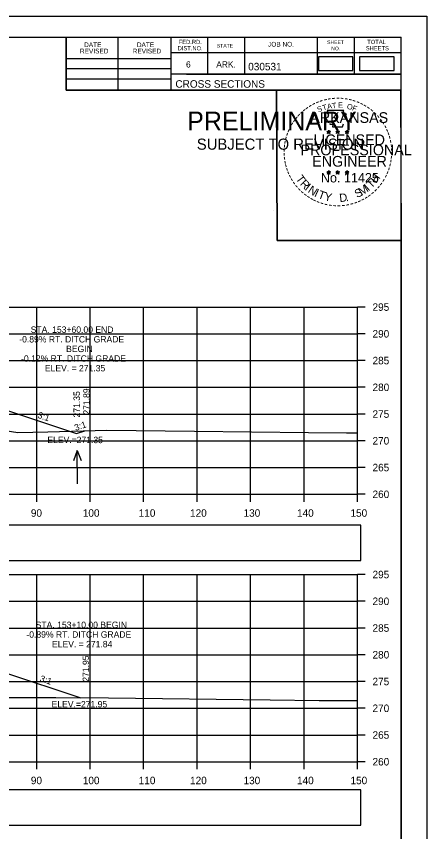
# Model space of a CAD drawing. Extents: x 285 to 4233, y -659 to 3710.
# Drawn here: x 1309.9 to 1386.6, y 19.8 to 172.2 of the extents above; entities that cross this region are included whole.
import ezdxf

# ---------------------------------------------------------------- set-up
doc = ezdxf.new("R2010")
doc.units = 0
for name, color, linetype in [('R_Axis', 7, 'Continuous'), ('R_Axis Annot', 7, 'Continuous'), ('R_Border', 7, 'Continuous'), ('R_Border PE', 7, 'Continuous'), ('R_Border Prem', 7, 'Continuous'), ('R_Exist Surface', 7, 'Continuous'), ('R_Fin Surface', 7, 'Continuous'), ('R_Grid', 7, 'Continuous'), ('R_No Plot', 7, 'Continuous'), ('R_Water Annot', 7, 'Continuous'), ('R_Xsect Elev', 7, 'Continuous'), ('R_Xsect Slope', 7, 'Continuous')]:
    doc.layers.add(name, color=color, linetype=linetype)

msp = doc.modelspace()

# ---------------------------------------------------------------- linework, layer by layer
at = {"layer": 'R_Axis'}
for p, q in [((1373.68, 82.87), (1373.68, 117.87)), ((1375.08, 117.87), (1373.68, 117.87)), ((1375.08, 112.87), (1373.68, 112.87)), ((1375.08, 107.87), (1373.68, 107.87)), ((1375.08, 102.87), (1373.68, 102.87)), ((1375.08, 97.87), (1373.68, 97.87)), ((1375.08, 92.87), (1373.68, 92.87)), ((1375.08, 87.87), (1373.68, 87.87)), ((1073.68, 82.87), (1373.68, 82.87)), ((1313.68, 81.47), (1313.68, 82.87)), ((1323.68, 81.47), (1323.68, 82.87)), ((1333.68, 81.47), (1333.68, 82.87)), ((1343.68, 81.47), (1343.68, 82.87)), ((1353.68, 81.47), (1353.68, 82.87)), ((1363.68, 81.47), (1363.68, 82.87)), ((1373.68, 81.47), (1373.68, 82.87)), ((1375.08, 82.87), (1373.68, 82.87)), ((1373.68, 32.87), (1373.68, 67.87)), ((1375.08, 67.87), (1373.68, 67.87)), ((1375.08, 62.87), (1373.68, 62.87)), ((1375.08, 57.87), (1373.68, 57.87)), ((1375.08, 52.87), (1373.68, 52.87)), ((1375.08, 47.87), (1373.68, 47.87)), ((1375.08, 42.87), (1373.68, 42.87)), ((1375.08, 37.87), (1373.68, 37.87)), ((1073.68, 32.87), (1373.68, 32.87)), ((1313.68, 31.47), (1313.68, 32.87)), ((1323.68, 31.47), (1323.68, 32.87)), ((1333.68, 31.47), (1333.68, 32.87)), ((1343.68, 31.47), (1343.68, 32.87)), ((1353.68, 31.47), (1353.68, 32.87)), ((1363.68, 31.47), (1363.68, 32.87)), ((1373.68, 31.47), (1373.68, 32.87)), ((1375.08, 32.87), (1373.68, 32.87))]:
    msp.add_line(p, q, dxfattribs=at)
at = {"layer": 'R_Axis Annot'}
for points in [[(1366.36, 162.12), (1372.81, 162.12), (1372.81, 164.68), (1366.36, 164.68)], [(1374.05, 162.12), (1380.51, 162.12), (1380.51, 164.68), (1374.05, 164.68)], [(1234.32, 70.47), (1374.32, 70.47), (1374.32, 77.12), (1234.32, 77.12)], [(1234.32, 20.99), (1374.32, 20.99), (1374.32, 27.65), (1234.32, 27.65)]]:
    msp.add_lwpolyline(points, close=True, dxfattribs=at)
at = {"layer": 'R_Border'}
for p, q in [((1065.68, 168.33), (1381.86, 168.33)), ((1319.22, 158.45), (1319.22, 168.33)), ((1328.9, 158.45), (1328.9, 168.33)), ((1338.76, 168.33), (1338.76, 158.45)), ((1345.6, 168.33), (1345.6, 161.39)), ((1352.54, 168.33), (1352.54, 161.39)), ((1366.12, 168.33), (1366.12, 161.39)), ((1373.06, 168.33), (1373.06, 161.39)), ((1381.86, -37.13), (1381.86, 168.33)), ((1381.86, 165.39), (1338.76, 165.39)), ((1381.86, 165.41), (1381.86, 165.41)), ((1319.22, 164.31), (1338.76, 164.31)), ((1319.22, 162.45), (1338.76, 162.45)), ((1319.22, 160.51), (1338.76, 160.51)), ((1381.86, 161.39), (1338.76, 161.39)), ((1341.72, 161.39), (1381.86, 161.39)), ((1381.86, 158.45), (1319.22, 158.45))]:
    msp.add_line(p, q, dxfattribs=at)
at = {"layer": 'R_Border PE'}
for p, q in [((1368.29, 150.96), (1368.25, 150.71)), ((1368.29, 150.6), (1368.29, 150.96)), ((1368.29, 150.96), (1368.34, 150.71)), ((1369.96, 150.96), (1369.92, 150.71)), ((1369.96, 150.6), (1369.96, 150.96)), ((1369.96, 150.96), (1370.01, 150.71)), ((1371.72, 150.95), (1371.68, 150.7)), ((1371.72, 150.59), (1371.72, 150.95)), ((1371.72, 150.95), (1371.77, 150.7)), ((1367.94, 150.71), (1368.29, 150.6)), ((1367.94, 150.71), (1368.19, 150.66)), ((1367.94, 150.71), (1368.18, 150.59)), ((1368.07, 150.3), (1368.29, 150.6)), ((1368.07, 150.3), (1368.2, 150.54)), ((1368.07, 150.3), (1368.29, 150.52)), ((1368.64, 150.71), (1368.29, 150.6)), ((1368.5, 150.3), (1368.29, 150.6)), ((1368.5, 150.3), (1368.29, 150.51)), ((1368.64, 150.71), (1368.35, 150.66)), ((1368.5, 150.3), (1368.37, 150.59)), ((1368.64, 150.71), (1368.43, 150.61)), ((1369.61, 150.71), (1369.96, 150.6)), ((1369.61, 150.71), (1369.86, 150.66)), ((1369.61, 150.71), (1369.85, 150.59)), ((1369.74, 150.3), (1369.96, 150.6)), ((1369.74, 150.3), (1369.87, 150.54)), ((1369.74, 150.3), (1369.96, 150.52)), ((1370.31, 150.71), (1369.96, 150.6)), ((1370.17, 150.3), (1369.96, 150.6)), ((1370.17, 150.3), (1369.96, 150.51)), ((1370.31, 150.71), (1370.02, 150.66)), ((1370.17, 150.3), (1370.04, 150.59)), ((1370.31, 150.71), (1370.1, 150.61)), ((1371.38, 150.7), (1371.72, 150.59)), ((1371.38, 150.7), (1371.63, 150.65)), ((1371.38, 150.7), (1371.61, 150.57)), ((1371.51, 150.29), (1371.72, 150.59)), ((1371.51, 150.29), (1371.63, 150.53)), ((1371.51, 150.29), (1371.72, 150.51)), ((1372.07, 150.7), (1371.72, 150.59)), ((1371.94, 150.29), (1371.72, 150.59)), ((1371.94, 150.29), (1371.72, 150.5)), ((1372.07, 150.7), (1371.79, 150.65)), ((1371.94, 150.29), (1371.8, 150.58)), ((1372.07, 150.7), (1371.87, 150.59)), ((1368.29, 143.39), (1368.25, 143.14)), ((1368.29, 143.02), (1368.29, 143.39)), ((1368.29, 143.39), (1368.34, 143.14)), ((1369.96, 143.39), (1369.91, 143.14)), ((1369.96, 143.02), (1369.96, 143.39)), ((1369.96, 143.39), (1370, 143.14)), ((1371.72, 143.38), (1371.68, 143.13)), ((1371.72, 143.01), (1371.72, 143.38)), ((1371.72, 143.38), (1371.77, 143.13)), ((1367.94, 143.14), (1368.29, 143.02)), ((1367.94, 143.14), (1368.19, 143.09)), ((1367.94, 143.14), (1368.17, 143.01)), ((1368.07, 142.73), (1368.29, 143.02)), ((1368.07, 142.73), (1368.2, 142.97)), ((1368.07, 142.73), (1368.28, 142.94)), ((1368.5, 142.73), (1368.28, 142.94)), ((1368.63, 143.14), (1368.29, 143.02)), ((1368.5, 142.73), (1368.29, 143.02)), ((1368.63, 143.14), (1368.35, 143.09)), ((1368.5, 142.73), (1368.36, 143.02)), ((1368.63, 143.14), (1368.43, 143.03)), ((1369.61, 143.14), (1369.96, 143.02)), ((1369.61, 143.14), (1369.86, 143.09)), ((1369.61, 143.14), (1369.84, 143.01)), ((1369.74, 142.73), (1369.96, 143.02)), ((1369.74, 142.73), (1369.87, 142.97)), ((1369.74, 142.73), (1369.95, 142.94)), ((1370.17, 142.73), (1369.95, 142.94)), ((1370.3, 143.14), (1369.96, 143.02)), ((1370.17, 142.73), (1369.96, 143.02)), ((1370.3, 143.14), (1370.02, 143.09)), ((1370.17, 142.73), (1370.03, 143.02)), ((1370.3, 143.14), (1370.1, 143.03)), ((1371.37, 143.13), (1371.72, 143.01)), ((1371.37, 143.13), (1371.63, 143.08)), ((1371.37, 143.13), (1371.61, 143)), ((1371.51, 142.72), (1371.72, 143.01)), ((1371.51, 142.72), (1371.63, 142.96)), ((1371.51, 142.72), (1371.72, 142.93)), ((1372.07, 143.13), (1371.72, 143.01)), ((1371.94, 142.72), (1371.72, 143.01)), ((1371.94, 142.72), (1371.72, 142.93)), ((1372.07, 143.13), (1371.78, 143.08)), ((1371.94, 142.72), (1371.8, 143.01)), ((1372.07, 143.13), (1371.87, 143.02))]:
    msp.add_line(p, q, dxfattribs=at)
for points in [[(1367.98, 154.59), (1368.25, 153.76)], [(1371.49, 153.66), (1371.64, 153.95), (1370.95, 153.92), (1371.1, 154.59), (1367.98, 154.59)], [(1368.29, 150.96), (1368.5, 150.3), (1367.94, 150.71), (1368.64, 150.71), (1368.07, 150.3), (1368.29, 150.96)], [(1368.47, 152.16), (1368.47, 152.08), (1369.04, 152.06), (1368.98, 151.58), (1370.85, 151.58), (1371.05, 152.12)], [(1369.96, 150.96), (1370.17, 150.3), (1369.61, 150.71), (1370.31, 150.71), (1369.74, 150.3), (1369.96, 150.96)], [(1371.72, 150.95), (1371.94, 150.29), (1371.38, 150.7), (1372.07, 150.7), (1371.51, 150.29), (1371.72, 150.95)], [(1368.29, 143.39), (1368.5, 142.73), (1367.94, 143.14), (1368.63, 143.14), (1368.07, 142.73), (1368.29, 143.39)], [(1369.96, 143.39), (1370.17, 142.73), (1369.61, 143.14), (1370.3, 143.14), (1369.74, 142.73), (1369.96, 143.39)], [(1371.72, 143.38), (1371.94, 142.72), (1371.37, 143.13), (1372.07, 143.13), (1371.51, 142.72), (1371.72, 143.38)]]:
    msp.add_lwpolyline(points, dxfattribs=at)
for centre, radius in [((1368.29, 150.6), 0.172), ((1368.29, 150.6), 0.145), ((1368.29, 150.6), 0.116), ((1368.29, 150.6), 0.0991), ((1368.29, 150.6), 0.0747), ((1368.29, 150.6), 0.0495), ((1368.29, 150.6), 0.0296), ((1369.96, 150.6), 0.172), ((1369.96, 150.6), 0.145), ((1369.96, 150.6), 0.116), ((1369.96, 150.6), 0.0991), ((1369.96, 150.6), 0.0747), ((1369.96, 150.6), 0.0495), ((1369.96, 150.6), 0.0296), ((1371.72, 150.58), 0.172), ((1371.72, 150.58), 0.145), ((1371.72, 150.58), 0.116), ((1371.72, 150.58), 0.0991), ((1371.72, 150.58), 0.0747), ((1371.72, 150.58), 0.0495), ((1371.72, 150.58), 0.0296), ((1368.29, 143.02), 0.172), ((1368.29, 143.02), 0.145), ((1368.29, 143.02), 0.116), ((1368.29, 143.02), 0.0991), ((1368.29, 143.02), 0.0747), ((1368.29, 143.02), 0.0495), ((1368.29, 143.02), 0.0296), ((1369.95, 143.02), 0.172), ((1369.95, 143.02), 0.145), ((1369.95, 143.02), 0.116), ((1369.95, 143.02), 0.0991), ((1369.95, 143.02), 0.0747), ((1369.95, 143.02), 0.0495), ((1369.95, 143.02), 0.0296), ((1371.72, 143.01), 0.172), ((1371.72, 143.01), 0.145), ((1371.72, 143.01), 0.116), ((1371.72, 143.01), 0.0991), ((1371.72, 143.01), 0.0747), ((1371.72, 143.01), 0.0495), ((1371.72, 143.01), 0.0296)]:
    msp.add_circle(centre, radius, dxfattribs=at)
at = {"layer": 'R_Exist Surface'}
for points in [[(1300.6, 95.89), (1310.15, 94.42), (1315.75, 94.57), (1326.78, 94.88), (1343.19, 94.68), (1364.49, 94.41), (1371.63, 94.35), (1373.68, 94.33)], [(1228.68, 45.41), (1234.67, 46.62), (1239.3, 47.25), (1244.95, 47.94), (1247.03, 48.04), (1249.91, 48.16), (1251.33, 48.21), (1254.08, 48.32), (1258.36, 48.26), (1266.51, 48.15), (1274.39, 48.02), (1278.28, 47.96), (1285.08, 47.6), (1288.11, 47.45), (1289.62, 47.64), (1290.05, 47.68), (1291.58, 47.42), (1298.28, 46.34), (1307.22, 44.9), (1317.24, 44.85), (1327.13, 44.8), (1357.34, 44.45), (1366.52, 44.35), (1373.68, 44.31)]]:
    msp.add_lwpolyline(points, dxfattribs=at)
at = {"layer": 'R_Fin Surface'}
for points in [[(1213.69, 95.31), (1223.68, 98.63), (1247.68, 102.63), (1253.68, 102.87), (1277.68, 102.39), (1279.68, 102.35), (1287.68, 102.03), (1307.68, 98.7), (1321.1, 94.23), (1322.71, 94.76)], [(1213.5, 45.48), (1223.68, 48.87), (1247.68, 52.87), (1253.68, 53.11), (1277.68, 52.96), (1279.68, 52.95), (1287.68, 52.9), (1307.68, 49.57), (1321.91, 44.83)]]:
    msp.add_lwpolyline(points, dxfattribs=at)
at = {"layer": 'R_Grid'}
for p, q in [((1073.68, 117.87), (1373.68, 117.87)), ((1313.68, 82.87), (1313.68, 117.87)), ((1323.68, 82.87), (1323.68, 117.87)), ((1333.68, 82.87), (1333.68, 117.87)), ((1343.68, 82.87), (1343.68, 117.87)), ((1353.68, 82.87), (1353.68, 117.87)), ((1363.68, 82.87), (1363.68, 117.87)), ((1373.68, 82.87), (1373.68, 117.87)), ((1073.68, 112.87), (1373.68, 112.87)), ((1073.68, 107.87), (1373.68, 107.87)), ((1073.68, 102.87), (1373.68, 102.87)), ((1073.68, 97.87), (1373.68, 97.87)), ((1073.68, 92.87), (1373.68, 92.87)), ((1073.68, 87.87), (1373.68, 87.87)), ((1073.68, 82.87), (1373.68, 82.87)), ((1073.68, 67.87), (1373.68, 67.87)), ((1313.68, 32.87), (1313.68, 67.87)), ((1323.68, 32.87), (1323.68, 67.87)), ((1333.68, 32.87), (1333.68, 67.87)), ((1343.68, 32.87), (1343.68, 67.87)), ((1353.68, 32.87), (1353.68, 67.87)), ((1363.68, 32.87), (1363.68, 67.87)), ((1373.68, 32.87), (1373.68, 67.87)), ((1073.68, 62.87), (1373.68, 62.87)), ((1073.68, 57.87), (1373.68, 57.87)), ((1073.68, 52.87), (1373.68, 52.87)), ((1073.68, 47.87), (1373.68, 47.87)), ((1073.68, 42.87), (1373.68, 42.87)), ((1073.68, 37.87), (1373.68, 37.87)), ((1073.68, 32.87), (1373.68, 32.87))]:
    msp.add_line(p, q, dxfattribs=at)
at = {"layer": 'R_No Plot'}
for p, q in [((1053.28, 172.23), (1386.61, 172.23)), ((1357.89, 136), (1357.89, 136))]:
    msp.add_line(p, q, dxfattribs=at)
for points in [[(1053.27, 172.23), (1386.61, 172.23), (1386.61, -41.11), (1053.27, -41.11)], [(1299.6, 168.33), (1319.22, 168.33), (1319.22, 158.45), (1335.33, 158.45), (1358.53, 158.45), (1358.65, 130.3), (1381.86, 130.3), (1381.86, -37.13), (1065.68, -37.13), (1065.68, 168.33)], [(1358.53, 158.45), (1381.74, 158.45), (1381.86, 130.3), (1358.65, 130.3)]]:
    msp.add_lwpolyline(points, close=True, dxfattribs=at)
at = {"layer": 'R_Water Annot'}
for p, q in [((1321.25, 91.08), (1320.58, 89.15)), ((1321.34, 84.8), (1321.25, 91.08)), ((1321.25, 91.08), (1321.98, 89.17))]:
    msp.add_line(p, q, dxfattribs=at)

# ---------------------------------------------------------------- texts
at = {"layer": 'R_Axis Annot'}
for s, p in [('295', (1376.48, 117.17)), ('290', (1376.48, 112.17)), ('285', (1376.48, 107.17)), ('280', (1376.48, 102.17)), ('275', (1376.48, 97.17)), ('270', (1376.48, 92.17)), ('265', (1376.48, 87.17)), ('260', (1376.48, 82.17)), ('90', (1312.59, 78.67)), ('100', (1322.3, 78.67)), ('110', (1332.76, 78.67)), ('120', (1342.36, 78.67)), ('130', (1352.36, 78.67)), ('140', (1362.36, 78.67)), ('150', (1372.36, 78.67)), ('295', (1376.48, 67.17)), ('290', (1376.48, 62.17)), ('285', (1376.48, 57.17)), ('280', (1376.48, 52.17)), ('275', (1376.48, 47.17)), ('270', (1376.48, 42.17)), ('265', (1376.48, 37.17)), ('260', (1376.48, 32.17)), ('90', (1312.59, 28.67)), ('100', (1322.3, 28.67)), ('110', (1332.76, 28.67)), ('120', (1342.36, 28.67)), ('130', (1352.36, 28.67)), ('140', (1362.36, 28.67)), ('150', (1372.36, 28.67))]:
    msp.add_text(s, height=1.4, dxfattribs=at).set_placement(p)
at = {"layer": 'R_Border'}
for s, height, p in [('FED.RD.', 0.782, (1340.24, 167.05)), ('SHEET', 0.684, (1367.98, 167.05)), ('TOTAL', 0.782, (1375.5, 167.05)), ('REVISED', 0.879, (1321.77, 165.29)), ('DATE', 0.879, (1322.55, 166.47)), ('REVISED', 0.879, (1331.63, 165.29)), ('DATE', 0.879, (1332.41, 166.47)), ('DIST.NO.', 0.782, (1340.04, 165.87)), ('STATE', 0.684, (1347.36, 166.37)), ('JOB NO.', 0.879, (1356.94, 166.57)), ('NO.', 0.684, (1368.76, 165.87)), ('SHEETS', 0.782, (1375.22, 165.87)), ('6', 1.17, (1341.6, 162.65)), ('ARK.', 1.172, (1347.26, 162.65)), ('030531', 1.4, (1353.23, 162.13)), ('CROSS SECTIONS', 1.4, (1339.62, 158.88))]:
    msp.add_text(s, height=height, rotation=360, dxfattribs=at).set_placement(p)
at = {"layer": 'R_Border PE'}
for s, height, rotation, p in [('-', 1.6, 0.1862, (1369.66, 156.3)), ('-', 1.6, 34.0636, (1364.87, 154.76)), ('-', 1.6, 28.7918, (1365.46, 155.13)), ('-', 1.6, 24.3072, (1366.1, 155.44)), ('-', 1.6, 19.1761, (1366.73, 155.71)), ('T', 1, 16.4036, (1367.25, 154.6)), ('-', 1.6, 13.6301, (1367.48, 155.95)), ('A', 1, 11.2132, (1368.08, 154.85)), ('-', 1.6, 10.2193, (1368.16, 156.12)), ('T', 1, 6.0228, (1368.93, 155.01)), ('-', 1.6, 5.8968, (1368.89, 156.23)), ('E', 1, 0.8323, (1370.03, 155.12)), ('-', 1.6, 357.743, (1370.38, 156.29)), ('-', 1.6, 352.1617, (1371.13, 156.23)), ('O', 1, 350.4515, (1371.64, 154.91)), ('-', 1.6, 347.2049, (1371.85, 156.12)), ('F', 1, 340.0707, (1372.59, 154.68)), ('-', 1.6, 342.3362, (1372.48, 155.96)), ('-', 1.6, 337.8551, (1373.22, 155.74)), ('-', 1.6, 334.1211, (1373.85, 155.47)), ('-', 1.6, 329.6409, (1374.43, 155.18)), ('-', 1.6, 48.423, (1362.93, 153.09)), ('-', 1.6, 42.9622, (1363.38, 153.57)), ('-', 1.6, 38.9507, (1363.81, 153.98)), ('-', 1.6, 36.2317, (1364.29, 154.36)), ('ARKANSAS', 2, 360, (1364.84, 152.3)), ('S', 1, 21.594, (1366.34, 154.26)), ('-', 1.6, 325.8627, (1375.07, 154.82)), ('-', 1.6, 320.5297, (1375.68, 154.4)), ('-', 1.6, 315.5786, (1376.28, 153.91)), ('-', 1.6, 54.2325, (1362.12, 152.04)), ('-', 1.6, 50.6142, (1362.53, 152.6)), ('-', 1.6, 309.8797, (1376.85, 153.36)), ('-', 1.6, 306.6522, (1377.37, 152.76)), ('-', 1.4, 303.6753, (1377.86, 152.19)), ('-', 1.6, 67.7743, (1361.22, 150.28)), ('-', 1.6, 62.8713, (1361.48, 150.9)), ('-', 1.6, 58.0706, (1361.79, 151.51)), ('-', 1.6, 299.6684, (1378.18, 151.58)), ('-', 1.6, 294.6628, (1378.5, 150.97)), ('-', 1.6, 75.461, (1360.8, 148.94)), ('-', 1.6, 72.3945, (1361, 149.65)), ('LICENSED', 2, 360, (1365.43, 148.15)), ('DWB', 0.01, 360, (1368.28, 150.59)), ('DWB', 0.01, 360, (1369.95, 150.59)), ('DWB', 0.01, 360, (1371.71, 150.58)), ('-', 1.6, 290.5728, (1378.76, 150.39)), ('-', 1.6, 285.1233, (1378.99, 149.81)), ('-', 1.6, 85.1863, (1360.59, 147.54)), ('-', 1.6, 81.2013, (1360.67, 148.23)), ('PROFESSIONAL', 2, 360, (1363.01, 146.25)), ('-', 1.6, 280.5493, (1379.19, 149.07)), ('-', 1.6, 276.5962, (1379.35, 148.3)), ('-', 1.6, 94.1959, (1360.6, 146.11)), ('-', 1.6, 89.0622, (1360.57, 146.84)), ('-', 1.6, 274.3301, (1379.41, 147.58)), ('-', 1.6, 269.9407, (1379.45, 146.95)), ('-', 1.6, 98.9479, (1360.68, 145.44)), ('-', 1.6, 101.7149, (1360.81, 144.71)), ('ENGINEER', 2, 360, (1365.2, 144.12)), ('-', 1.6, 260.9953, (1379.36, 145.63)), ('-', 1.6, 263.5172, (1379.43, 146.28)), ('-', 1.6, 105.4578, (1360.97, 144.12)), ('-', 1.6, 109.0874, (1361.19, 143.48)), ('-', 1.6, 252.8681, (1379.07, 144.23)), ('-', 1.6, 255.7626, (1379.25, 144.95)), ('-', 1.6, 114.0643, (1361.44, 142.89)), ('-', 1.6, 115.7289, (1361.75, 142.27)), ('-', 1.6, 120.4471, (1362.1, 141.68)), ('T', 1.54, 306.0406, (1362.05, 141.86)), ('No. 11425', 1.757, 360, (1366.82, 141.17)), ('DWB', 0.01, 360, (1368.27, 143.02)), ('DWB', 0.01, 360, (1369.94, 143.02)), ('DWB', 0.01, 360, (1371.71, 143.01)), ('T', 1.54, 46.6444, (1376.28, 139.96)), ('H', 1.54, 54.6088, (1377.17, 140.9)), ('-', 1.6, 239.0712, (1378.19, 142.18)), ('-', 1.6, 244.6197, (1378.58, 142.93)), ('-', 1.6, 247.8887, (1378.84, 143.56)), ('-', 1.6, 125.8934, (1362.51, 141.12)), ('-', 1.6, 130.7181, (1362.97, 140.57)), ('R', 1.54, 314.005, (1362.81, 140.81)), ('I', 1.54, 321.9694, (1363.71, 139.88)), ('N', 1.54, 326.5002, (1364.28, 139.41)), ('M', 1.54, 32.6563, (1374.43, 138.63)), ('I', 1.54, 42.1136, (1375.72, 139.48)), ('-', 1.6, 231.2538, (1377.36, 140.96)), ('-', 1.6, 233.8452, (1377.79, 141.52)), ('-', 1.6, 134.2238, (1363.49, 140.03)), ('-', 1.6, 138.9338, (1364.01, 139.56)), ('-', 1.6, 144.6463, (1364.57, 139.16)), ('I', 1.54, 335.3603, (1365.48, 138.63)), ('T', 1.54, 339.8912, (1366.15, 138.3)), ('Y', 1.54, 347.8556, (1367.36, 137.85)), ('D', 1.54, 6.3969, (1370.35, 137.49)), ('S', 1.54, 26.9312, (1373.59, 138.22)), ('-', 1.6, 215.7363, (1375.81, 139.41)), ('-', 1.6, 221.0851, (1376.35, 139.88)), ('-', 1.6, 225.7653, (1376.88, 140.39)), ('-', 1.6, 148.0898, (1365.13, 138.79)), ('-', 1.6, 151.5704, (1365.71, 138.46)), ('-', 1.6, 154.6002, (1366.23, 138.21)), ('-', 1.6, 158.5612, (1366.85, 137.96)), ('-', 1.6, 162.7983, (1367.54, 137.75)), ('-', 1.6, 167.5555, (1368.26, 137.58)), ('.', 1.54, 13.7642, (1371.54, 137.62)), ('-', 1.6, 195.4743, (1372.79, 137.85)), ('-', 1.6, 200.7184, (1373.47, 138.09)), ('-', 1.6, 204.2516, (1374.09, 138.36)), ('-', 1.6, 207.3568, (1374.71, 138.68)), ('-', 1.6, 212.2491, (1375.27, 139.03)), ('-', 1.6, 173.1155, (1369.03, 137.47)), ('-', 1.6, 176.5183, (1369.78, 137.42)), ('-', 1.6, 181.5918, (1370.52, 137.44)), ('-', 1.6, 185.8167, (1371.33, 137.51)), ('-', 1.6, 191.2858, (1372.06, 137.65))]:
    msp.add_text(s, height=height, rotation=rotation, dxfattribs=at).set_placement(p)
at = {"layer": 'R_Border Prem'}
for s, height, p in [('PRELIMINARY', 3.5, (1341.81, 150.92)), ('DWB', 0.01, (1342.55, 152.77)), ('SUBJECT TO REVISION', 2.0751, (1343.62, 147.29))]:
    msp.add_text(s, height=height, rotation=360, dxfattribs=at).set_placement(p)
at = {"layer": 'R_Xsect Elev'}
for s, p in [('STA. 153+60.00 END', (1312.56, 113.05)), ('-0.89% RT. DITCH GRADE', (1310.42, 111.25)), ('BEGIN', (1319.18, 109.45)), ('-0.12% RT. DITCH GRADE', (1310.76, 107.65)), ('ELEV. = 271.35', (1315.21, 105.85)), ('ELEV.=271.35', (1315.67, 92.43)), ('STA. 153+10.00 BEGIN ', (1313.49, 57.86)), ('-0.89% RT. DITCH GRADE', (1311.75, 56.06)), ('ELEV. = 271.84', (1316.54, 54.26)), ('ELEV.=271.95', (1316.47, 43.03))]:
    msp.add_text(s, height=1.2, dxfattribs=at).set_placement(p)
for s, p in [('271.89', (1323.59, 97.76)), ('271.35', (1321.76, 97.23)), ('271.95', (1323.46, 47.83))]:
    msp.add_text(s, height=1.2, rotation=90, dxfattribs=at).set_placement(p)
at = {"layer": 'R_Xsect Slope'}
for rotation, p in [(341.5626, (1313.76, 97.2)), (18.4364, (1320.96, 94.71)), (341.5639, (1314.16, 47.94))]:
    msp.add_text('3:1', height=1.2, rotation=rotation, dxfattribs=at).set_placement(p)

doc.saveas('drawing.dxf')
